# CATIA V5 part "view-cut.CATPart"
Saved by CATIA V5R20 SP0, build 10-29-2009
Part number: Part1
Bounding box of the stored display mesh (mm): x -65 to 65, y -40 to 80, z 0 to 120
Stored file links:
  J:\카티아자료\수업자료\툴바예제\3 Drafting\cut.CATPart
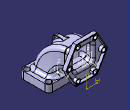
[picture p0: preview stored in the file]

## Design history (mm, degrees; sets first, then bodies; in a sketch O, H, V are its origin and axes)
AxisSystem1 "Absolute Axis System": origin (0, 0, 0), X (1, 0, 0), Y (0, 1, 0), Z (0, 0, 1)
AxisSystem2: origin (0, 80, 70), X (1, 0, 0), Y (0, 1, 0), Z (0, 0, 1)
Set1
  Sketch1 on XY plane of AxisSystem1, origin (0, 0, 0), H (1, 0, 0), V (0, 1, 0)
    line L1 (50, 25) -> (50, -25)
    line L2 (50, -25) -> (-50, -25)
    line L3 (-50, -25) -> (-50, 25)
    line L4 (-50, 25) -> (50, 25)
    length L1 = 50
    length L2 = 100
    vertical: L1 V, L3 V
    horizontal: L2 H, L4 H
    equidistance: L1 L3 O, L2 L4 O
  Sketch2 on YZ plane of AxisSystem1, origin (0, 0, 0), H (0, 1, 0), V (0, 0, 1)
    line L1 (0, 0) -> (0, 20)
    arc A1 centre (50, 20) radius 50 from (0, 20) to (50, 70) cw
    line L2 (50, 70) -> (80, 70)
    point P4 (80, 70)
    length L1 = 20
    radius A1 = 50
    length L2 = 30
    vertical: L1 V
    tangency: A1 L1, L2 A1
    horizontal: L2 H
  Plane1: type Normal, Curve Sketch2.L2, RefPoint Sketch2.P4
  Sketch3 on Plane1, origin (0, 80, 0), H (1, 0, 0), V (0, 0, 1)
    point P1 (0, 70)
    line L1 (25, 95) -> (25, 45)
    line L2 (25, 45) -> (-25, 45)
    line L3 (-25, 45) -> (-25, 95)
    line L4 (-25, 95) -> (25, 95)
    reference projected point E1 (0, 70) from Sketch2.P4
    length L1 = 50
    length L2 = 50
    coincidence: P1 V, P1 E1
    vertical: L1 V, L3 V
    horizontal: L2 H, L4 H
    equidistance: L1 L3 P1, L2 L4 P1
Body1 (main body)
  Loft1: solid, Sections (Sketch3; Sketch1), Spine Sketch2
  Sketch4 on face of Loft1, origin (0, 80, 0), H (-1, 0, 0), V (0, 0, 1)
    point P1 (0, 70)
    point P2 (28.8675, 120)
    point P3 (-28.8675, 120)
    point P4 (-57.735, 70)
    point P5 (-28.8675, 20)
    point P6 (28.8675, 20)
    point P7 (57.735, 70)
    point P8 (0, 120)
    line L1 (28.8675, 120) -> (-28.8675, 120)
    line L2 (-28.8675, 120) -> (-57.735, 70)
    line L3 (-57.735, 70) -> (-28.8675, 20)
    line L4 (-28.8675, 20) -> (28.8675, 20)
    line L5 (28.8675, 20) -> (57.735, 70)
    line L6 (57.735, 70) -> (28.8675, 120)
    construction line L7 (0, 70) -> (0, 120)
    construction circle A1 centre (0, 70) radius 57.735
    construction arc A2 centre (28.8675, 20) radius 57.735 from (-28.8675, 20) to (57.735, 70) cw
    construction arc A3 centre (-28.8675, 120) radius 57.735 from (-57.735, 70) to (28.8675, 120) ccw
    axis line L8 (0, 70) -> (72.1485, 70)
    reference projected line E1 (-25, 95) -> (25, 95) from edge [face of Loft1 | face of Loft1]
    reference projected line E2 (25, 45) -> (-25, 45) from edge [face of Loft1 | face of Loft1]
    distance L1 L4 = 100
    coincidence: P1 V, A1 P2, A1 P3, A1 P4, A1 P5, A1 P6, A1 P7, A2 P1, A3 P1
    vertical: L7 V
    midpoint: P8 L1
    horizontal: L8 H
    symmetry: E1 E2 L8
  Pad1: profile Sketch4, direction (0, -1, 0), length 10
  Sketch5 on face of Loft1, origin (0, 0, 0), H (1, 0, 0), V (0, -1, 0)
    line L1 (65, 40) -> (65, -40)
    line L2 (65, -40) -> (-65, -40)
    line L3 (-65, -40) -> (-65, 40)
    line L4 (-65, 40) -> (65, 40)
    length L1 = 80
    length L4 = 130
    vertical: L1 V, L3 V
    horizontal: L2 H, L4 H
    equidistance: L1 L3 O, L2 L4 O
  Pad2: profile Sketch5, direction (0, 0, 1), length 20
  Fillet1: radius 10, on edge [face of Loft1 | face of Loft1] (x4)
  Fillet2: radius 5, on edge [face of Loft1 | end face of Pad1]
  Fillet3: radius 10, on edge [face of Pad2 from Sketch5.L2 | face of Pad2 from Sketch5.L1]; edge [face of Pad2 from Sketch5.L1 | face of Pad2 from Sketch5.L4]; edge [face of Pad2 from Sketch5.L4 | face of Pad2 from Sketch5.L3]; edge [face of Pad2 from Sketch5.L3 | face of Pad2 from Sketch5.L2]
  Sketch6 on face of Pad1, origin (0, 80, 0), H (-1, 0, 0), V (0, 0, 1)
    point P1 (0, 70)
    reference projected line E1 (28.8675, 120) -> (-28.8675, 120) from edge [face of Pad1 from Sketch4.L1 | start face of Pad1]
    distance P1 E1 = 50
    coincidence: P1 V
  Sketch7 on ZX plane of AxisSystem2, origin (0, 80, 70), H (0, 0, 1), V (1, 0, 0)
    circle A1 centre (40.7032, -23.5) radius 5
    axis line L1 (40.7032, -23.5) -> (0, 0)
    reference projected point E1 (50, -28.8675) from vertex [face of Pad1 from Sketch4.L6 | face of Pad1 from Sketch4.L1 | end face of Pad1]
    radius A1 = 5
    length L1 = 47
    coincidence: L1 E1
  Pocket1: profile Sketch7, direction (0, -1, 0), length 20
  CircPattern1: of Pocket1, instances 6, angular step 60, axis from edge [YZ plane of AxisSystem2 | XY plane of AxisSystem2]
  Shell1: IntOffset 2, Face (face of Pad2; face of Pad1), ExtOffset 0
  RemoveFace1: RemoveFaces (face of Shell1; face of Shell1; face of Shell1; face of Shell1; face of Shell1; face of Shell1; face of Shell1; face of Shell1; face of Shell1)
  Sketch8 on end face of Pad2, origin (0, 0, 20), H (1, 0, 0), V (0, 1, 0)
    circle A1 centre (55, 30) radius 7.5
    reference projected arc E1 centre (55, 30) radius 10 from (65, 30) to (55, 40) ccw from edge [end face of Pad2 | face of Fillet3]
    radius A1 = 7.5
    concentricity: A1 E1
  Pocket2: profile Sketch8, direction (0, 0, -1), length 20
  RectPattern1: of Pocket2, direction 1 instances 2, spacing 110, along end face of Pad2, direction 2 instances 2, spacing 60, along end face of Pad2
  Fillet4: radius 10, on edge [face of Loft1 | end face of Pad2]
  Sketch9 on YZ plane of AxisSystem1, origin (0, 0, 0), H (0, 1, 0), V (0, 0, 1)
    line L1 (41.1967, 90) -> (0, 90)
    arc A1 centre (0, 80) radius 10 from (0, 90) to (-10, 80) ccw
    point P3 (0, 80)
    line L2 (-10, 80) -> (-10, 41.2458)
    reference intersected line E1 through (80, 0) direction (0, 1) from ZX plane of AxisSystem2
    distance P3 H = 80
    distance P3 E1 = 80
    radius A1 = 10
    horizontal: L1 H
    tangency: A1 L1, L2 A1
    vertical: L2 V
  Stiffener1: ThicknessValue 10, ExtendedProfile Sketch9, ThicknessTop 0
  Sketch10 on face of Stiffener1, origin (-5, 0, 0), H (0, -1, 0), V (0, 0, 1)
    circle A1 centre (3, 83) radius 2.5
    point P1 (3, 83)
    reference projected line E1 (-23.0733, 90) -> (0, 90) from edge [face of Stiffener1 | face of Stiffener1 from Sketch9.L1]
    reference projected line E2 (10, 80) -> (10, 65.0001) from edge [face of Stiffener1 | face of Stiffener1 from Sketch9.L2]
    radius A1 = 2.5
    distance E1 P1 = 7
    distance E2 P1 = 7
  Pocket3: profile Sketch10, direction (1, 0, 0), length 20
  Fillet5: radius 5, on edge [face of Stiffener1 | face of Loft1]; edge [face of Loft1 | face of Stiffener1]
  Fillet6: radius 1, on edge [face of Fillet5 | face of Stiffener1 from Sketch9.L2] (x2)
